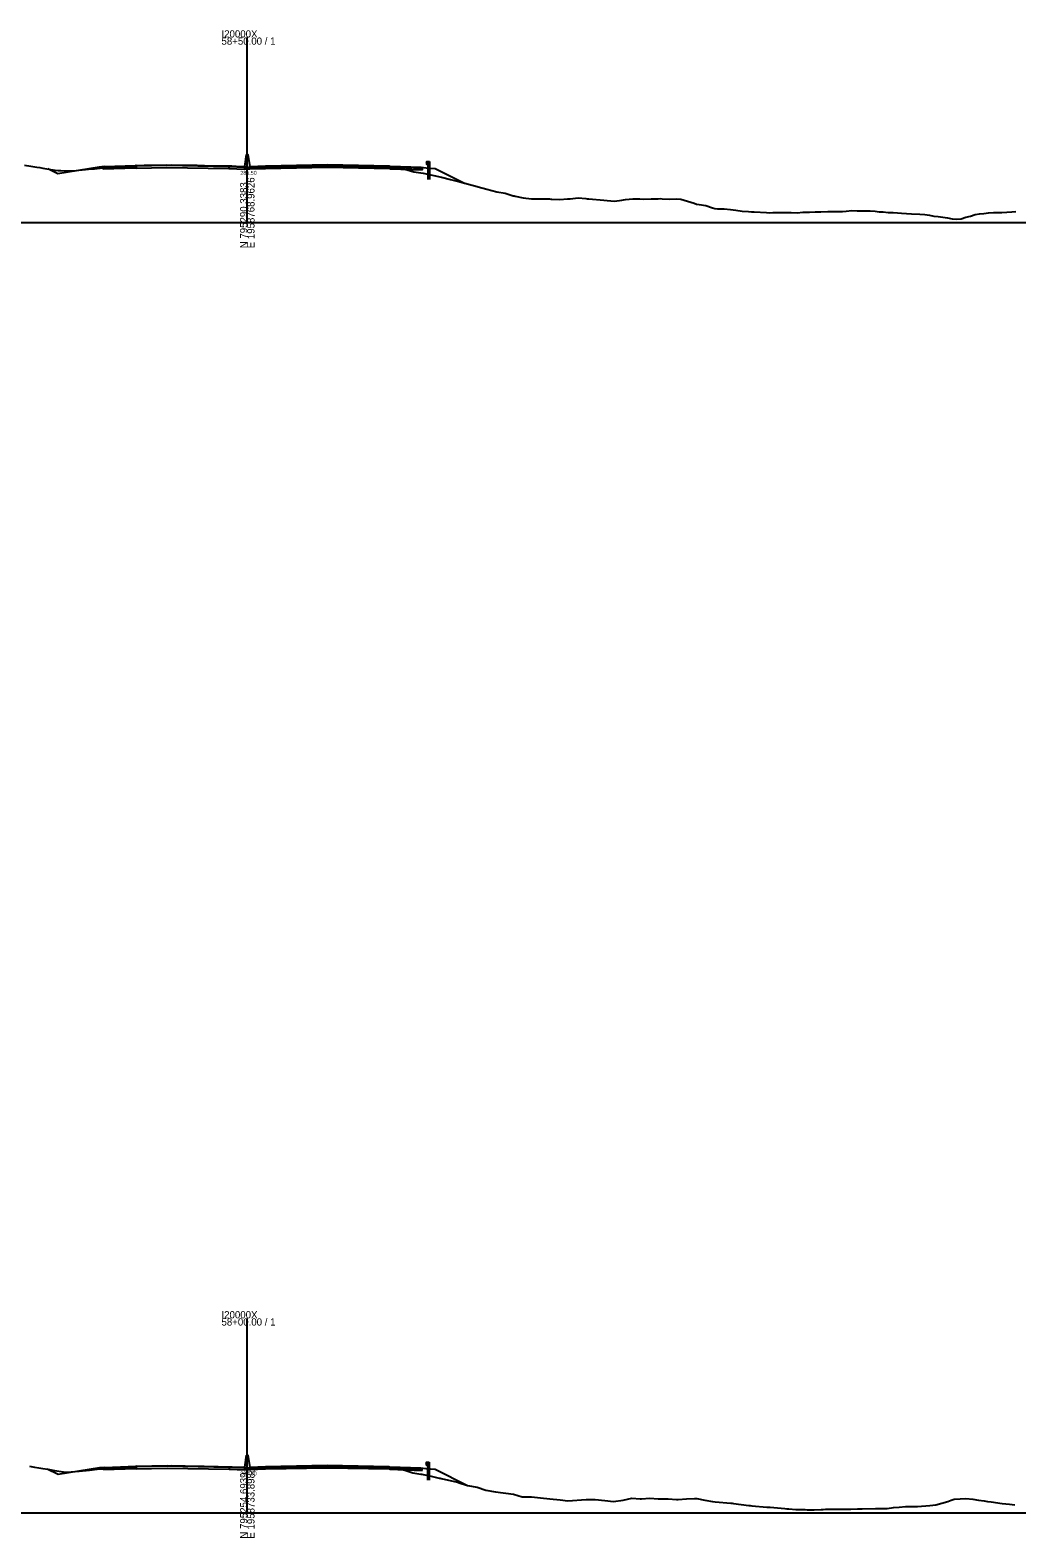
# Model space of a CAD drawing. Extents: x -4026 to 9638, y -10 to 19609.
# Drawn here: x -1734 to -1352, y 7990 to 8575 of the extents above; entities that cross this region are included whole.
import ezdxf

# ---------------------------------------------------------------- set-up
doc = ezdxf.new("R2010")
doc.units = 0
for name, color, linetype in [('RD_GPK_XS_Cell', 7, 'Continuous'), ('RD_XS_Base', 7, 'Continuous'), ('RD_XS_ExGround', 7, 'Continuous'), ('RD_XS_GR', 7, 'Continuous'), ('RD_XS_Greenside', 7, 'Continuous'), ('RD_XS_MedBWall', 7, 'Continuous'), ('RD_XS_Pave', 7, 'Continuous'), ('RD_XS_PaveOvlay', 7, 'Continuous'), ('RD_XS_TieSlope', 7, 'Continuous'), ('RD_XS_TX_Elev_EX', 7, 'Continuous')]:
    doc.layers.add(name, color=color, linetype=linetype)

msp = doc.modelspace()

# ---------------------------------------------------------------- linework, layer by layer
at = {"layer": 'RD_GPK_XS_Cell'}
for p, q in [((-1650, 8500), (-1650, 8571.68)), ((-2000, 8500), (-1650, 8500)), ((-1650, 8500), (-1300, 8500)), ((-1650, 8000), (-1650, 8075.36)), ((-2000, 8000), (-1650, 8000)), ((-1650, 8000), (-1300, 8000))]:
    msp.add_line(p, q, dxfattribs=at)
at = {"layer": 'RD_XS_Base'}
for points in [[(-1705.87, 8521.28), (-1705.37, 8521.3), (-1693.37, 8521.78)], [(-1705.87, 8520.61), (-1705.87, 8521.28)], [(-1693.37, 8521.11), (-1705.87, 8520.61)], [(-1693.37, 8521.78), (-1693.12, 8521.78)], [(-1693.37, 8521.11), (-1693.37, 8521.78)], [(-1693.12, 8521.11), (-1693.37, 8521.11)], [(-1657.12, 8521.54), (-1681.12, 8522.03), (-1693.12, 8521.78)], [(-1693.12, 8521.78), (-1693.12, 8521.11)], [(-1693.12, 8521.11), (-1681.12, 8521.36), (-1657.12, 8520.87)], [(-1651, 8521.31), (-1657.12, 8521.54)], [(-1657.12, 8521.54), (-1657.12, 8520.87)], [(-1657.12, 8520.87), (-1651, 8520.64)], [(-1651, 8520.64), (-1651, 8521.31)], [(-1649, 8521.28), (-1642.88, 8521.52)], [(-1649, 8520.61), (-1649, 8521.28)], [(-1642.88, 8520.85), (-1649, 8520.61)], [(-1642.88, 8521.52), (-1618.88, 8522.01), (-1594.88, 8521.52)], [(-1642.88, 8520.85), (-1642.88, 8521.52)], [(-1594.88, 8520.85), (-1618.88, 8521.34), (-1642.88, 8520.85)], [(-1594.88, 8521.52), (-1594.63, 8521.52)], [(-1594.88, 8520.85), (-1594.88, 8521.52)], [(-1594.63, 8520.85), (-1594.88, 8520.85)], [(-1594.63, 8521.52), (-1594.63, 8520.85)], [(-1582.13, 8521.02), (-1582.63, 8521.04), (-1594.63, 8521.52)], [(-1594.63, 8520.85), (-1582.13, 8520.35)], [(-1582.13, 8520.35), (-1582.13, 8521.02)], [(-1705.75, 8017.28), (-1705.25, 8017.3), (-1693.25, 8017.77)], [(-1705.75, 8016.61), (-1705.75, 8017.28)], [(-1693.25, 8017.1), (-1705.75, 8016.61)], [(-1693.25, 8017.77), (-1693, 8017.78)], [(-1693.25, 8017.1), (-1693.25, 8017.77)], [(-1693, 8017.11), (-1693.25, 8017.1)], [(-1657, 8017.54), (-1681, 8018.02), (-1693, 8017.78)], [(-1693, 8017.78), (-1693, 8017.11)], [(-1693, 8017.11), (-1681, 8017.35), (-1657, 8016.87)], [(-1651, 8017.31), (-1657, 8017.54)], [(-1657, 8017.54), (-1657, 8016.87)], [(-1657, 8016.87), (-1651, 8016.64)], [(-1651, 8016.64), (-1651, 8017.31)], [(-1649, 8017.31), (-1643, 8017.55)], [(-1649, 8016.64), (-1649, 8017.31)], [(-1643, 8016.88), (-1649, 8016.64)], [(-1643, 8017.55), (-1619, 8018.03), (-1595, 8017.55)], [(-1643, 8016.88), (-1643, 8017.55)], [(-1595, 8016.88), (-1619, 8017.36), (-1643, 8016.88)], [(-1595, 8017.55), (-1594.75, 8017.54)], [(-1595, 8016.88), (-1595, 8017.55)], [(-1594.75, 8016.87), (-1595, 8016.88)], [(-1594.75, 8017.54), (-1594.75, 8016.87)], [(-1582.25, 8017.05), (-1582.75, 8017.07), (-1594.75, 8017.54)], [(-1594.75, 8016.87), (-1582.25, 8016.38)], [(-1582.25, 8016.38), (-1582.25, 8017.05)]]:
    msp.add_lwpolyline(points, dxfattribs=at)
at = {"layer": 'RD_XS_ExGround'}
for points in [[(-1736.29, 8522.25), (-1733.95, 8521.88), (-1731.58, 8521.45), (-1730.42, 8521.27), (-1729.27, 8521.07), (-1726.88, 8520.69), (-1724.45, 8520.33), (-1723.35, 8520.17), (-1722.26, 8520.1), (-1717.32, 8520.07), (-1716.28, 8520.13), (-1715.25, 8520.23), (-1712.74, 8520.52), (-1710.19, 8520.75), (-1709.2, 8520.85), (-1708.23, 8520.95), (-1705.67, 8521.23), (-1700.97, 8521.57), (-1699.7, 8521.65), (-1690.55, 8522.12), (-1690.2, 8522.14), (-1689.82, 8522.15), (-1679.2, 8522.35), (-1669.47, 8522.15), (-1667.45, 8522.1), (-1666.63, 8522.09), (-1655.94, 8521.89), (-1654.27, 8521.76), (-1650.73, 8521.51), (-1650, 8521.5), (-1648.56, 8521.48), (-1646.75, 8521.46), (-1645.02, 8521.56), (-1641.21, 8521.78), (-1635.03, 8521.93), (-1629.67, 8522.05), (-1620, 8522.18), (-1617.94, 8522.21), (-1611.55, 8522.05), (-1606.42, 8521.94), (-1605.43, 8521.9), (-1598.25, 8521.63), (-1592.53, 8521.36), (-1588.99, 8520.63), (-1585.46, 8519.69), (-1581.86, 8519.09), (-1574.73, 8517.54), (-1571.31, 8516.63), (-1567.6, 8515.7), (-1564.24, 8514.9), (-1560.94, 8513.93), (-1560.47, 8513.81), (-1557.17, 8512.97), (-1553.34, 8511.92), (-1550.1, 8511.3), (-1546.92, 8510.39), (-1546.56, 8510.3), (-1546.21, 8510.2), (-1543.03, 8509.55), (-1539.9, 8509.17), (-1539.08, 8509.12), (-1532.89, 8509.11), (-1532.42, 8509.09), (-1531.95, 8509.06), (-1528.89, 8508.92), (-1525.87, 8509.11), (-1525.35, 8509.13), (-1524.82, 8509.22), (-1521.81, 8509.5), (-1518.86, 8509.28), (-1518.28, 8509.19), (-1517.69, 8509.14), (-1511.85, 8508.64), (-1510.56, 8508.54), (-1507.67, 8508.32), (-1504.83, 8508.71), (-1504.14, 8508.8), (-1503.43, 8508.89), (-1500.6, 8509.21), (-1497.82, 8509.1), (-1496.3, 8509.07), (-1493.53, 8509.16), (-1490.81, 8509.22), (-1489.99, 8509.24), (-1489.17, 8509.21), (-1486.46, 8509.06), (-1483.79, 8509.12), (-1482.04, 8509.01), (-1476.78, 8507.51), (-1475.85, 8507.12), (-1474.91, 8506.99), (-1472.32, 8506.57), (-1469.77, 8505.65), (-1468.78, 8505.38), (-1467.78, 8505.35), (-1465.24, 8505.29), (-1462.75, 8505.06), (-1460.65, 8504.74), (-1458.17, 8504.4), (-1455.74, 8504.2), (-1454.64, 8504.19), (-1453.52, 8504.11), (-1448.72, 8503.87), (-1447.57, 8503.79), (-1446.39, 8503.81), (-1444.03, 8503.82), (-1441.71, 8503.86), (-1440.49, 8503.84), (-1439.26, 8503.84), (-1436.96, 8503.75), (-1434.7, 8503.95), (-1432.13, 8504.03), (-1429.89, 8504.09), (-1427.68, 8504.14), (-1425, 8504.2), (-1420.67, 8504.25), (-1419.28, 8504.3), (-1417.87, 8504.43), (-1415.74, 8504.58), (-1413.66, 8504.55), (-1410.74, 8504.51), (-1408.67, 8504.51), (-1406.64, 8504.35), (-1405.14, 8504.16), (-1403.61, 8504.07), (-1401.6, 8503.83), (-1399.63, 8503.81), (-1398.07, 8503.7), (-1396.48, 8503.63), (-1394.53, 8503.45), (-1392.61, 8503.37), (-1389.35, 8503.25), (-1387.46, 8503.09), (-1385.6, 8502.82), (-1383.92, 8502.47), (-1382.22, 8502.34), (-1378.59, 8501.76), (-1376.85, 8501.45), (-1375.09, 8501.3), (-1373.32, 8501.42), (-1371.57, 8502.09), (-1369.78, 8502.5), (-1367.96, 8503.04), (-1366.25, 8503.32), (-1364.56, 8503.45), (-1362.71, 8503.76), (-1360.83, 8503.84), (-1359.17, 8503.93), (-1357.55, 8503.9), (-1353.7, 8504.09), (-1352.1, 8504.24)], [(-1734.36, 8018.09), (-1732.5, 8017.75), (-1730.83, 8017.5), (-1729.18, 8017.23), (-1727.29, 8016.91), (-1725.37, 8016.56), (-1723.76, 8016.27), (-1722.17, 8016.02), (-1720.22, 8015.76), (-1718.24, 8015.83), (-1715.16, 8016.09), (-1711.11, 8016.54), (-1708.14, 8016.87), (-1706.08, 8017.1), (-1701.79, 8017.44), (-1699.62, 8017.6), (-1698.25, 8017.67), (-1690.14, 8018.09), (-1686.4, 8018.17), (-1679.19, 8018.33), (-1668.86, 8018.09), (-1667.51, 8018.06), (-1666.68, 8018.05), (-1655.82, 8017.86), (-1654.2, 8017.75), (-1650.62, 8017.51), (-1650, 8017.5), (-1648.39, 8017.49), (-1646.64, 8017.47), (-1642.31, 8017.72), (-1641.23, 8017.77), (-1638.12, 8017.84), (-1629.47, 8018.03), (-1622.83, 8018.12), (-1617.59, 8018.2), (-1610.26, 8018.03), (-1606.41, 8017.93), (-1602.37, 8017.78), (-1598.22, 8017.62), (-1597.27, 8017.56), (-1592.94, 8017.3), (-1589.9, 8016.75), (-1589.4, 8016.66), (-1588.91, 8016.49), (-1585.87, 8015.55), (-1582.77, 8014.99), (-1582.33, 8014.93), (-1581.9, 8014.84), (-1578.8, 8014.18), (-1575.64, 8013.48), (-1575.26, 8013.39), (-1574.88, 8013.33), (-1568.51, 8011.83), (-1567.87, 8011.63), (-1564.65, 8010.63), (-1560.85, 8009.89), (-1557.58, 8008.84), (-1553.84, 8008.12), (-1546.83, 8007.27), (-1543.44, 8006.22), (-1539.81, 8006.19), (-1536.37, 8005.75), (-1532.8, 8005.43), (-1528.81, 8005.02), (-1525.74, 8004.71), (-1518.61, 8005.14), (-1515.15, 8005.18), (-1511.48, 8004.75), (-1508.08, 8004.44), (-1504.35, 8004.92), (-1501.01, 8005.65), (-1497.73, 8005.44), (-1497.22, 8005.44), (-1493.94, 8005.74), (-1490.72, 8005.48), (-1490.4, 8005.47), (-1490.09, 8005.44), (-1486.87, 8005.46), (-1483.7, 8005.22), (-1483.33, 8005.22), (-1482.96, 8005.2), (-1479.8, 8005.42), (-1476.69, 8005.56), (-1475.83, 8005.54), (-1472.73, 8004.91), (-1469.68, 8004.39), (-1468.7, 8004.27), (-1462.66, 8003.75), (-1462.12, 8003.7), (-1461.57, 8003.61), (-1458.58, 8003.19), (-1455.65, 8002.88), (-1455.05, 8002.83), (-1454.44, 8002.75), (-1448.63, 8002.22), (-1447.31, 8002.14), (-1441.62, 8001.65), (-1440.9, 8001.6), (-1440.18, 8001.56), (-1437.37, 8001.35), (-1434.61, 8001.26), (-1433.83, 8001.23), (-1433.05, 8001.2), (-1430.3, 8001.22), (-1427.59, 8001.29), (-1426.76, 8001.32), (-1425.92, 8001.38), (-1420.58, 8001.48), (-1418.79, 8001.47), (-1416.16, 8001.47), (-1413.57, 8001.53), (-1412.62, 8001.52), (-1411.66, 8001.51), (-1406.55, 8001.64), (-1405.55, 8001.66), (-1404.53, 8001.67), (-1402.01, 8001.72), (-1399.54, 8002.11), (-1397.4, 8002.25), (-1394.94, 8002.48), (-1392.52, 8002.46), (-1391.41, 8002.45), (-1390.27, 8002.43), (-1385.51, 8002.8), (-1384.33, 8002.92), (-1383.14, 8003.11), (-1380.8, 8003.74), (-1378.5, 8004.41), (-1377.26, 8004.95), (-1376.01, 8005.26), (-1373.73, 8005.42), (-1371.48, 8005.49), (-1368.88, 8005.32), (-1366.66, 8004.9), (-1364.47, 8004.63), (-1363.12, 8004.41), (-1361.75, 8004.27), (-1357.46, 8003.68), (-1356.05, 8003.5), (-1354.62, 8003.3), (-1352.51, 8003.08)]]:
    msp.add_lwpolyline(points, dxfattribs=at)
at = {"layer": 'RD_XS_GR'}
for points in [[(-1580.38, 8523.61), (-1580.62, 8523.31)], [(-1580.62, 8523.31), (-1580.39, 8523.01)], [(-1580.39, 8523.01), (-1580.62, 8522.73)], [(-1580.62, 8522.73), (-1580.38, 8522.43)], [(-1580.38, 8522.43), (-1580.38, 8523.61)], [(-1580.38, 8523.61), (-1579.89, 8523.61)], [(-1579.89, 8522.43), (-1580.38, 8522.43)], [(-1579.89, 8523.61), (-1579.4, 8523.61)], [(-1579.89, 8521.15), (-1579.89, 8523.61)], [(-1579.89, 8523.61), (-1579.89, 8522.43)], [(-1579.89, 8516.65), (-1579.89, 8521.15)], [(-1579.89, 8521.15), (-1579.4, 8521.11)], [(-1579.4, 8521.11), (-1579.89, 8521.15)], [(-1579.4, 8523.61), (-1579.4, 8521.11)], [(-1579.4, 8521.11), (-1579.4, 8516.65)], [(-1580.51, 8019.63), (-1580.75, 8019.33)], [(-1580.75, 8019.33), (-1580.52, 8019.03)], [(-1580.52, 8019.03), (-1580.75, 8018.75)], [(-1580.75, 8018.75), (-1580.51, 8018.45)], [(-1580.51, 8018.45), (-1580.51, 8019.63)], [(-1580.51, 8019.63), (-1580.02, 8019.63)], [(-1580.02, 8018.45), (-1580.51, 8018.45)], [(-1580.02, 8019.63), (-1579.52, 8019.63)], [(-1580.02, 8017.17), (-1580.02, 8019.63)], [(-1580.02, 8019.63), (-1580.02, 8018.45)], [(-1580.02, 8012.67), (-1580.02, 8017.17)], [(-1580.02, 8017.17), (-1579.52, 8017.13)], [(-1579.52, 8017.13), (-1580.02, 8017.17)], [(-1579.52, 8019.63), (-1579.52, 8017.13)], [(-1579.52, 8017.13), (-1579.52, 8012.67)]]:
    msp.add_lwpolyline(points, dxfattribs=at)
at = {"layer": 'RD_XS_Greenside'}
for points in [[(-1707.37, 8521.48), (-1723.37, 8518.81)], [(-1705.37, 8521.64), (-1707.37, 8521.48)], [(-1582.63, 8521.37), (-1580.63, 8521.21)], [(-1580.63, 8521.21), (-1577.13, 8520.92), (-1565.87, 8515.29)], [(-1707.25, 8017.47), (-1723.25, 8014.8)], [(-1705.25, 8017.63), (-1707.25, 8017.47)], [(-1582.75, 8017.4), (-1580.75, 8017.23)], [(-1580.75, 8017.23), (-1577.25, 8016.94), (-1564.62, 8010.63)]]:
    msp.add_lwpolyline(points, dxfattribs=at)
at = {"layer": 'RD_XS_MedBWall'}
for points in [[(-1651, 8521.64), (-1650.25, 8526.31)], [(-1650.25, 8526.31), (-1649.75, 8526.31), (-1649, 8521.6)], [(-1651, 8520.6), (-1651, 8521.31), (-1651, 8521.64)], [(-1649, 8520.6), (-1651, 8520.6)], [(-1649, 8521.6), (-1649, 8521.28), (-1649, 8520.6)], [(-1651, 8017.64), (-1650.25, 8022.31)], [(-1650.25, 8022.31), (-1649.75, 8022.31), (-1649, 8017.63)], [(-1651, 8016.63), (-1651, 8017.31), (-1651, 8017.64)], [(-1649, 8016.63), (-1651, 8016.63)], [(-1649, 8017.63), (-1649, 8017.31), (-1649, 8016.63)]]:
    msp.add_lwpolyline(points, dxfattribs=at)
at = {"layer": 'RD_XS_Pave'}
for points in [[(-1705.37, 8521.47), (-1693.37, 8521.95)], [(-1693.37, 8521.78), (-1705.37, 8521.3)], [(-1705.37, 8521.3), (-1705.37, 8521.47)], [(-1693.37, 8521.95), (-1693.12, 8521.95)], [(-1693.37, 8521.78), (-1693.37, 8521.95)], [(-1693.12, 8521.78), (-1693.37, 8521.78)], [(-1693.12, 8521.95), (-1681.12, 8522.19), (-1657.12, 8521.71)], [(-1657.12, 8521.54), (-1681.12, 8522.03), (-1693.12, 8521.78)], [(-1693.12, 8521.95), (-1693.12, 8521.78)], [(-1657.12, 8521.71), (-1657.12, 8521.54)], [(-1657.12, 8521.71), (-1651, 8521.48)], [(-1651, 8521.31), (-1657.12, 8521.54)], [(-1651, 8521.48), (-1651, 8521.31)], [(-1642.88, 8521.69), (-1649, 8521.45)], [(-1649, 8521.28), (-1642.88, 8521.52)], [(-1649, 8521.45), (-1649, 8521.28)], [(-1594.88, 8521.69), (-1618.88, 8522.17), (-1642.88, 8521.69)], [(-1642.88, 8521.52), (-1618.88, 8522.01), (-1594.88, 8521.52)], [(-1642.88, 8521.69), (-1642.88, 8521.52)], [(-1594.88, 8521.69), (-1594.63, 8521.69)], [(-1594.88, 8521.52), (-1594.88, 8521.69)], [(-1594.63, 8521.52), (-1594.88, 8521.52)], [(-1594.63, 8521.69), (-1594.63, 8521.52)], [(-1582.63, 8521.21), (-1594.63, 8521.69)], [(-1594.63, 8521.52), (-1582.63, 8521.04)], [(-1582.63, 8521.04), (-1582.63, 8521.21)], [(-1705.25, 8017.46), (-1693.25, 8017.94)], [(-1693.25, 8017.77), (-1705.25, 8017.3)], [(-1705.25, 8017.3), (-1705.25, 8017.46)], [(-1693.25, 8017.94), (-1693, 8017.95)], [(-1693.25, 8017.77), (-1693.25, 8017.94)], [(-1693, 8017.78), (-1693.25, 8017.77)], [(-1693, 8017.95), (-1681, 8018.19), (-1657, 8017.71)], [(-1657, 8017.54), (-1681, 8018.02), (-1693, 8017.78)], [(-1693, 8017.95), (-1693, 8017.78)], [(-1657, 8017.71), (-1657, 8017.54)], [(-1657, 8017.71), (-1651, 8017.48)], [(-1651, 8017.31), (-1657, 8017.54)], [(-1651, 8017.48), (-1651, 8017.31)], [(-1643, 8017.72), (-1649, 8017.48)], [(-1649, 8017.31), (-1643, 8017.55)], [(-1649, 8017.48), (-1649, 8017.31)], [(-1595, 8017.72), (-1619, 8018.2), (-1643, 8017.72)], [(-1643, 8017.55), (-1619, 8018.03), (-1595, 8017.55)], [(-1643, 8017.72), (-1643, 8017.55)], [(-1595, 8017.72), (-1594.75, 8017.71)], [(-1595, 8017.55), (-1595, 8017.72)], [(-1594.75, 8017.54), (-1595, 8017.55)], [(-1594.75, 8017.71), (-1594.75, 8017.54)], [(-1582.75, 8017.23), (-1594.75, 8017.71)], [(-1594.75, 8017.54), (-1582.75, 8017.07)], [(-1582.75, 8017.07), (-1582.75, 8017.23)]]:
    msp.add_lwpolyline(points, dxfattribs=at)
at = {"layer": 'RD_XS_PaveOvlay'}
for points in [[(-1705.37, 8521.64), (-1693.37, 8522.12)], [(-1693.37, 8521.95), (-1705.37, 8521.47)], [(-1705.37, 8521.47), (-1705.37, 8521.64)], [(-1693.37, 8522.12), (-1693.37, 8521.95)], [(-1693.12, 8522.12), (-1693.37, 8522.12)], [(-1693.37, 8521.95), (-1693.12, 8521.95)], [(-1693.12, 8522.12), (-1681.12, 8522.36), (-1657.12, 8521.88)], [(-1657.12, 8521.71), (-1681.12, 8522.19), (-1693.12, 8521.95)], [(-1693.12, 8521.95), (-1693.12, 8522.12)], [(-1657.12, 8521.88), (-1657.12, 8521.71)], [(-1657.12, 8521.88), (-1651, 8521.64)], [(-1651, 8521.48), (-1657.12, 8521.71)], [(-1651, 8521.64), (-1651, 8521.48)], [(-1642.88, 8521.86), (-1649, 8521.6)], [(-1649, 8521.45), (-1642.88, 8521.69)], [(-1649, 8521.6), (-1649, 8521.45)], [(-1594.88, 8521.86), (-1618.88, 8522.34), (-1642.88, 8521.86)], [(-1642.88, 8521.69), (-1618.88, 8522.17), (-1594.88, 8521.69)], [(-1642.88, 8521.86), (-1642.88, 8521.69)], [(-1594.88, 8521.69), (-1594.88, 8521.86)], [(-1594.88, 8521.86), (-1594.63, 8521.85)], [(-1594.63, 8521.69), (-1594.88, 8521.69)], [(-1594.63, 8521.85), (-1594.63, 8521.69)], [(-1594.63, 8521.85), (-1582.63, 8521.37)], [(-1582.63, 8521.21), (-1594.63, 8521.69)], [(-1582.63, 8521.37), (-1582.63, 8521.21)], [(-1705.25, 8017.63), (-1693.25, 8018.11)], [(-1693.25, 8017.94), (-1705.25, 8017.46)], [(-1705.25, 8017.46), (-1705.25, 8017.63)], [(-1693, 8018.12), (-1693.25, 8018.11)], [(-1693.25, 8018.11), (-1693.25, 8017.94)], [(-1693.25, 8017.94), (-1693, 8017.95)], [(-1693, 8018.12), (-1681, 8018.36), (-1657, 8017.88)], [(-1657, 8017.71), (-1681, 8018.19), (-1693, 8017.95)], [(-1693, 8017.95), (-1693, 8018.12)], [(-1657, 8017.88), (-1657, 8017.71)], [(-1657, 8017.88), (-1651, 8017.64)], [(-1651, 8017.48), (-1657, 8017.71)], [(-1651, 8017.64), (-1651, 8017.48)], [(-1643, 8017.88), (-1649, 8017.63)], [(-1649, 8017.48), (-1643, 8017.72)], [(-1649, 8017.63), (-1649, 8017.48)], [(-1595, 8017.88), (-1619, 8018.36), (-1643, 8017.88)], [(-1643, 8017.72), (-1619, 8018.2), (-1595, 8017.72)], [(-1643, 8017.88), (-1643, 8017.72)], [(-1595, 8017.72), (-1595, 8017.88)], [(-1595, 8017.88), (-1594.75, 8017.88)], [(-1594.75, 8017.71), (-1595, 8017.72)], [(-1594.75, 8017.88), (-1594.75, 8017.71)], [(-1594.75, 8017.88), (-1582.75, 8017.4)], [(-1582.75, 8017.23), (-1594.75, 8017.71)], [(-1582.75, 8017.4), (-1582.75, 8017.23)]]:
    msp.add_lwpolyline(points, dxfattribs=at)
at = {"layer": 'RD_XS_TieSlope'}
for points in [[(-1723.37, 8518.81), (-1727.26, 8520.75)], [(-1723.25, 8014.8), (-1727.55, 8016.95)]]:
    msp.add_lwpolyline(points, dxfattribs=at)

# ---------------------------------------------------------------- texts
at = {"layer": 'RD_GPK_XS_Cell'}
for s, p in [('58+50.00 / 1', (-1660, 8568.88)), ('I20000X', (-1660, 8571.68)), ('58+00.00 / 1', (-1660, 8072.56)), ('I20000X', (-1660, 8075.36))]:
    msp.add_text(s, height=2.8, dxfattribs=at).set_placement(p)
for s, p in [('N 795290.3383', (-1650, 8490)), ('E 1958768.9626', (-1647.2, 8490)), ('E 1958733.8988', (-1647.2, 7990)), ('N 795254.6939', (-1650, 7990))]:
    msp.add_text(s, height=2.8, rotation=90, dxfattribs=at).set_placement(p)
at = {"layer": 'RD_XS_TX_Elev_EX'}
for s, p in [('285.50', (-1652.69, 8518.5)), ('287.50', (-1652.69, 8014.5))]:
    msp.add_text(s, height=1.5, dxfattribs=at).set_placement(p)

doc.saveas('drawing.dxf')
